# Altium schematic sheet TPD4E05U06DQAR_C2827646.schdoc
size 127 x 101 mm
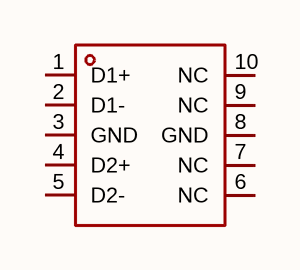
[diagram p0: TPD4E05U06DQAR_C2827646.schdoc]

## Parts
U?  tpd4e05u06dqar_c2827646  [USON-10_L2.5-W1.0-P0.50-BL]  (value not drawn)

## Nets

Not connected (* = marked no-connect by the designer): U? 1(D1+) 2(D1-) 3(GND) 4(D2+) 5(D2-) 6(NC) 7(NC) 8(GND) 9(NC) 10(NC)

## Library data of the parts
U? = tpd4e05u06dqar_c2827646: 极性:单向;反向截止电压(Vrwm):5.5V;钳位电压:13V;峰值脉冲电流(Ipp):5A;峰值脉冲功率(Ppp):70W@8/20us;击穿电压:7.5V;; Manufacturer: TECH PUBLIC(台舟); AddInBom: yes; ModelId: ab22a3507c584f4790945dcc3c1a797e; ModelName: USON-10_L2.5-W1.0-H0.6-P0.50; ModelTransform: 40.1574,98.425,0,90,0,0,0.001,0,0; Polarity: 单向; Reverse Stand-Off Voltage (Vrwm): 5.5V; Clamping Voltage: 13V; Peak Pulse Current (Ipp): 5A; Voltage - Breakdown: 7.5V; Reverse Leakage Current (Ir): 50nA; Number of Channels: 四路; level of protection: IEC 61000-4-2；IEC 61000-4-4；IEC 61000-4-5; Junction Capacitance: 0.6pF；0.3pF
